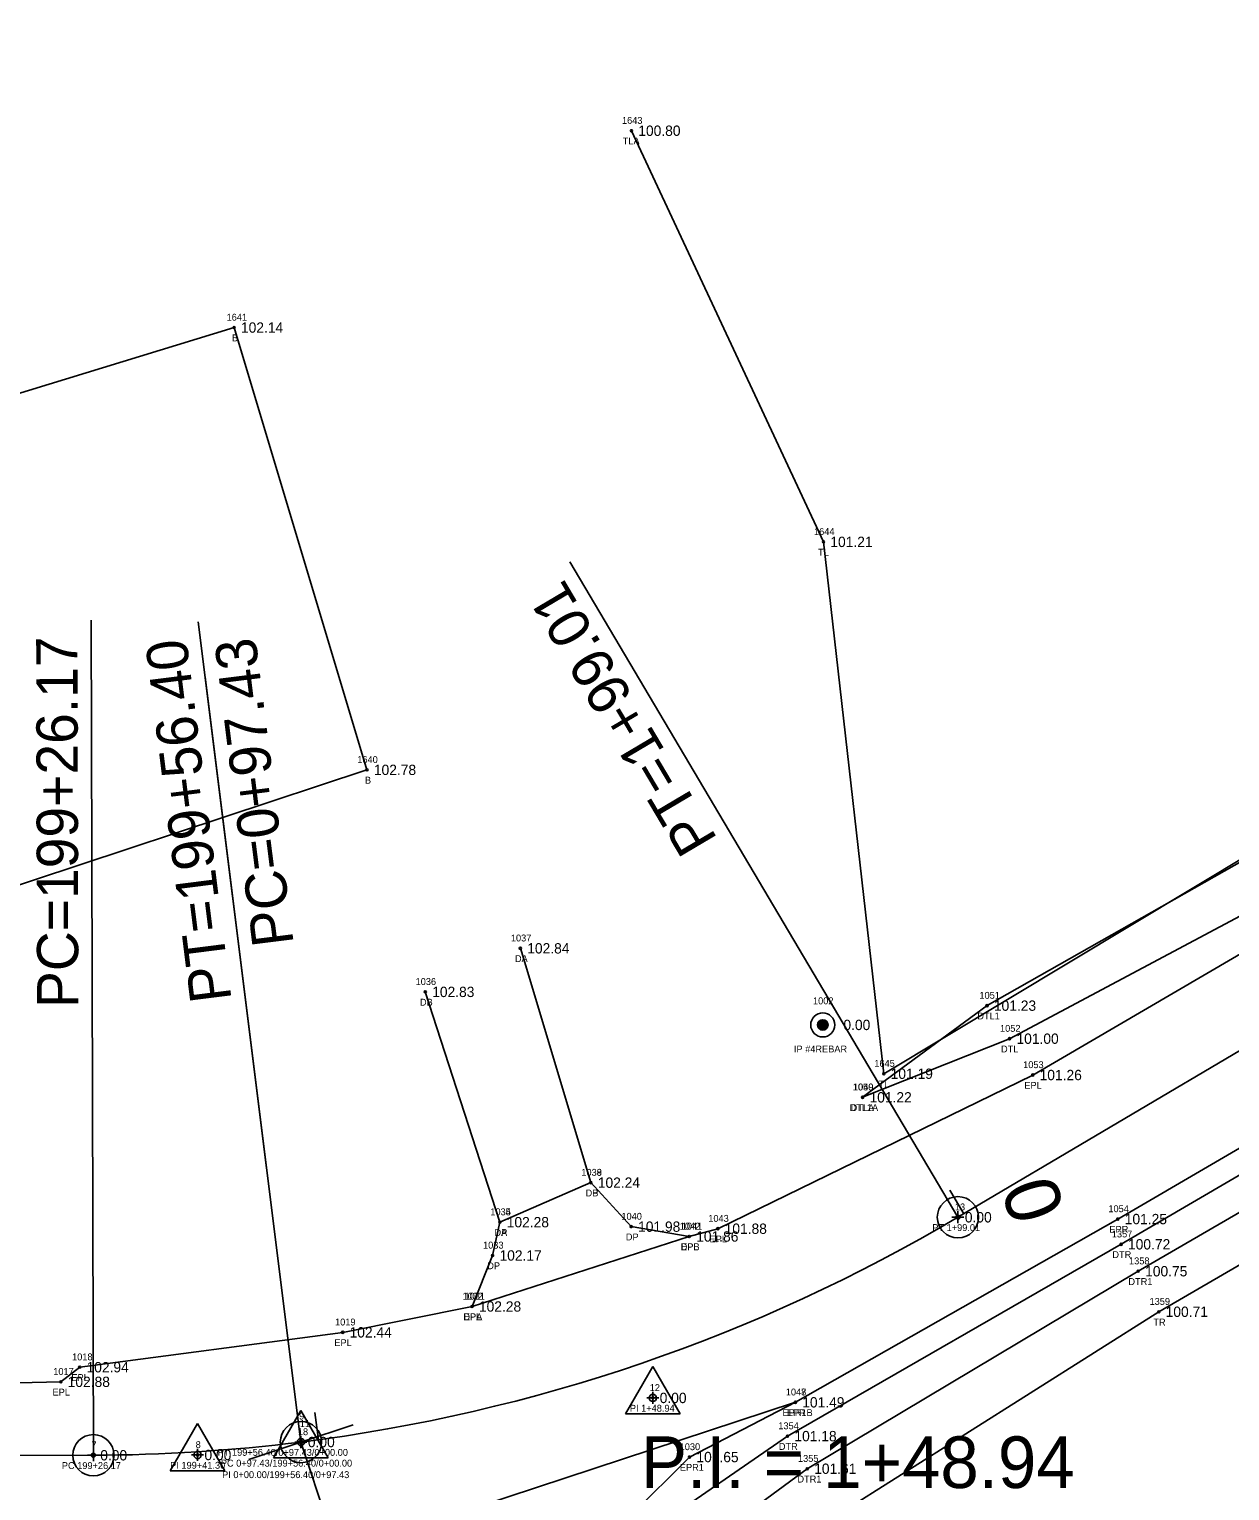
# Model space of a CAD drawing. Extents: x 2529517 to 2532038, y 935000 to 936944.
# Drawn here: x 2530422.1 to 2530596.5, y 935585.6 to 935798 of the extents above; entities that cross this region are included whole.
import ezdxf

# ---------------------------------------------------------------- set-up
doc = ezdxf.new("R2010")
doc.units = 0
for name, color, linetype in [('Default', 7, 'Continuous'), ('RD_EX_Bldg', 7, 'Continuous'), ('RD_EX_Bldg_txCode', 7, 'Continuous'), ('RD_EX_Driveway', 7, 'Continuous'), ('RD_EX_Driveway_txCode', 7, 'Continuous'), ('RD_EX_DV_Prop_txCode', 7, 'Continuous'), ('RD_EX_DV_PropPin', 7, 'Continuous'), ('RD_EX_H2O', 7, 'Continuous'), ('RD_EX_H2O_txCode', 7, 'Continuous'), ('RD_EX_Road', 7, 'Continuous'), ('RD_EX_Road_txCode', 7, 'Continuous'), ('RD_EX_TX_Bldg_ELEV', 7, 'Continuous'), ('RD_EX_TX_Driveway_ELEV', 7, 'Continuous'), ('RD_EX_TX_DV_Prop_ELEV', 7, 'Continuous'), ('RD_EX_TX_H2O_ELEV', 7, 'Continuous'), ('RD_EX_TX_Road_ELEV', 7, 'Continuous'), ('RD_EX_TX_VEG_ELEV', 7, 'Continuous'), ('RD_EX_VEG', 7, 'Continuous'), ('RD_EX_VEG_txCode', 7, 'Continuous'), ('RD_HC_Cl', 7, 'Continuous'), ('RD_HC_Data', 7, 'Continuous'), ('RD_HC_Data_Tic', 7, 'Continuous'), ('RD_HC_Survey_ELEV', 7, 'Continuous'), ('RD_HC_TX_Sta50', 7, 'Continuous'), ('RD_HC_txCode', 7, 'Continuous'), ('RD_SMD_Locator', 7, 'Continuous')]:
    doc.layers.add(name, color=color, linetype=linetype)

msp = doc.modelspace()

# ---------------------------------------------------------------- linework, layer by layer
at = {"layer": 'Default'}
for p, q in [((2530557.05, 935625.34), (2531768.07, 936342.55)), ((2530557.92, 935625.34), (2530556.17, 935625.34)), ((2530557.05, 935626.22), (2530557.05, 935624.47)), ((2530512.72, 935599.97), (2530512.72, 935598.22)), ((2530513.6, 935599.09), (2530511.85, 935599.09)), ((2530461.61, 935593.56), (2530461.61, 935591.81)), ((2530461.61, 935593.56), (2530461.61, 935591.81)), ((2530431.45, 935591.64), (2530431.45, 935589.89)), ((2530446.59, 935591.68), (2530446.59, 935589.93)), ((2530462.48, 935592.68), (2530460.73, 935592.68)), ((2530462.48, 935592.68), (2530460.73, 935592.68)), ((2530461.61, 935592.68), (2530556.12, 935307.96)), ((2530229.26, 935590.22), (2530431.45, 935590.76)), ((2530432.33, 935590.76), (2530430.58, 935590.76)), ((2530447.47, 935590.8), (2530445.72, 935590.8))]:
    msp.add_line(p, q, dxfattribs=at)
for start, end in [(277.1442, 300.6357), (277.1442, 300.6357), (270.1522, 277.1442), (270.1522, 277.1442)]:
    msp.add_arc((2530430.8, 935838.52), 247.76, start, end, dxfattribs=at)
at = {"layer": 'RD_EX_Bldg'}
msp.add_lwpolyline([(2530389.74, 935735.57), (2530408.79, 935669.73), (2530471.2, 935690.35), (2530451.89, 935754.62), (2530389.74, 935735.57)], dxfattribs=at)
at = {"layer": 'RD_EX_Driveway'}
for p, q in [((2530493.48, 935664.42), (2530503.73, 935630.37)), ((2530490.5, 935624.63), (2530479.67, 935658.09))]:
    msp.add_line(p, q, dxfattribs=at)
msp.add_lwpolyline([(2530486.46, 935612.38), (2530489.45, 935619.79), (2530490.5, 935624.63), (2530503.73, 935630.37), (2530509.58, 935623.98), (2530518.02, 935622.55)], dxfattribs=at)
at = {"layer": 'RD_EX_DV_PropPin'}
for p, q in [((2530536.68, 935653.1), (2530536.68, 935653.49)), ((2530536.71, 935653), (2530536.71, 935653.59)), ((2530536.75, 935652.92), (2530536.75, 935653.66)), ((2530536.78, 935652.87), (2530536.78, 935653.72)), ((2530536.82, 935652.82), (2530536.82, 935653.77)), ((2530536.85, 935652.78), (2530536.85, 935653.81)), ((2530536.89, 935652.74), (2530536.89, 935653.84)), ((2530536.92, 935652.71), (2530536.92, 935653.88)), ((2530536.96, 935652.68), (2530536.96, 935653.9)), ((2530536.99, 935652.66), (2530536.99, 935653.93)), ((2530537.03, 935652.64), (2530537.03, 935653.95)), ((2530537.06, 935652.62), (2530537.06, 935653.97)), ((2530537.1, 935652.6), (2530537.1, 935653.99)), ((2530537.13, 935652.59), (2530537.13, 935654)), ((2530537.17, 935652.57), (2530537.17, 935654.01)), ((2530537.2, 935652.56), (2530537.2, 935654.03)), ((2530537.24, 935652.55), (2530537.24, 935654.03)), ((2530537.27, 935652.55), (2530537.27, 935654.04)), ((2530537.31, 935652.54), (2530537.31, 935654.05)), ((2530537.34, 935652.54), (2530537.34, 935654.05)), ((2530537.38, 935652.53), (2530537.38, 935654.05)), ((2530537.41, 935652.53), (2530537.41, 935654.06)), ((2530537.45, 935652.53), (2530537.45, 935654.05)), ((2530537.48, 935652.54), (2530537.48, 935654.05)), ((2530537.52, 935652.54), (2530537.52, 935654.05)), ((2530537.55, 935652.55), (2530537.55, 935654.04)), ((2530537.59, 935652.55), (2530537.59, 935654.03)), ((2530537.62, 935652.56), (2530537.62, 935654.03)), ((2530537.66, 935652.57), (2530537.66, 935654.01)), ((2530537.69, 935652.59), (2530537.69, 935654)), ((2530537.73, 935652.6), (2530537.73, 935653.99)), ((2530537.76, 935652.62), (2530537.76, 935653.97)), ((2530537.8, 935652.64), (2530537.8, 935653.95)), ((2530537.83, 935652.66), (2530537.83, 935653.93)), ((2530537.87, 935652.68), (2530537.87, 935653.9)), ((2530537.9, 935652.71), (2530537.9, 935653.88)), ((2530537.94, 935652.74), (2530537.94, 935653.84)), ((2530537.97, 935652.78), (2530537.97, 935653.81)), ((2530538.01, 935652.82), (2530538.01, 935653.77)), ((2530538.04, 935652.87), (2530538.04, 935653.72)), ((2530538.08, 935652.92), (2530538.08, 935653.66)), ((2530538.11, 935653), (2530538.11, 935653.59)), ((2530538.15, 935653.1), (2530538.15, 935653.49))]:
    msp.add_line(p, q, dxfattribs=at)
for radius in [1.75, 0.761]:
    msp.add_circle((2530537.41, 935653.29), radius, dxfattribs=at)
at = {"layer": 'RD_EX_H2O'}
for points in [[(2530543.2, 935642.77), (2530561.27, 935656.09), (2530603.32, 935679.95), (2530687.23, 935730.15), (2530719.54, 935749.07), (2530726.45, 935748.92)], [(2530543.2, 935642.77), (2530564.55, 935651.29), (2530607.02, 935673.87), (2530692.01, 935723.47), (2530725.54, 935743.2), (2530726.45, 935748.92)], [(2530585.61, 935271.89), (2530554.63, 935366.84), (2530523, 935462.44), (2530497.71, 935534.53), (2530497.63, 935550.35), (2530501.9, 935567.07), (2530512.76, 935580.06), (2530532.29, 935593.54), (2530580.75, 935621.41), (2530622.78, 935645.99), (2530706.38, 935694.8)], [(2530592.81, 935273.73), (2530561.2, 935369.39), (2530529.39, 935464.13), (2530504.24, 935535.46), (2530502.94, 935549.83), (2530506.75, 935563.82), (2530516.63, 935575.2), (2530535.16, 935588.8), (2530583.24, 935617.5), (2530624.86, 935641.7), (2530708.31, 935690.59), (2530708.33, 935693.17), (2530706.38, 935694.8)]]:
    msp.add_lwpolyline(points, dxfattribs=at)
at = {"layer": 'RD_EX_Road'}
for points in [[(2530213.13, 935600.16), (2530313.8, 935600.81), (2530414.15, 935601.13), (2530426.72, 935601.43), (2530429.46, 935603.55), (2530467.67, 935608.62), (2530486.46, 935612.38), (2530518.02, 935622.55), (2530522.16, 935623.68), (2530567.91, 935646.01), (2530609.3, 935670.15), (2530695.46, 935720.02), (2530775.85, 935769.27), (2530868.29, 935824.03), (2530924.84, 935856.95), (2530956.21, 935875.82), (2531040.72, 935926.38), (2531079.45, 935947.76)], [(2530212.44, 935579.72), (2530312.61, 935580.14), (2530402.98, 935580.64), (2530451.06, 935579.53), (2530466.91, 935580.35), (2530487.45, 935583.29), (2530533.43, 935598.45), (2530580.28, 935625.08), (2530621.69, 935649.23), (2530704.62, 935698.35), (2530718.67, 935706.38), (2530795.45, 935752.36), (2530871.33, 935796.67), (2530882.4, 935803.04), (2530947.17, 935842.26), (2530966, 935852.42), (2530992.72, 935868), (2531009.49, 935879.01), (2531052.39, 935904.85), (2531090.88, 935928.23)], [(2530591.21, 935242.46), (2530571.43, 935300.61), (2530549.4, 935366.29), (2530518.07, 935460.9), (2530493.7, 935533.55), (2530494.46, 935557.42), (2530501.12, 935573.63), (2530518.05, 935590.5), (2530533.43, 935598.45)]]:
    msp.add_lwpolyline(points, dxfattribs=at)
at = {"layer": 'RD_EX_VEG'}
for points in [[(2530509.61, 935783.22), (2530537.51, 935723.48), (2530546.27, 935646.2), (2530689.77, 935732.43), (2530734.63, 935758.06), (2530721.39, 935783.29)], [(2530523.95, 935565.79), (2530539.5, 935582.04), (2530586.22, 935611.61), (2530720.44, 935689.62), (2530802.59, 935736.49), (2530863.89, 935770.01)]]:
    msp.add_lwpolyline(points, dxfattribs=at)
at = {"layer": 'RD_HC_Cl'}
for p, q in [((2530557.05, 935625.34), (2531768.07, 936342.55)), ((2530461.61, 935592.68), (2530556.12, 935307.96)), ((2530229.26, 935590.22), (2530431.45, 935590.76))]:
    msp.add_line(p, q, dxfattribs=at)
for start, end in [(277.1442, 300.6357), (270.1522, 277.1442)]:
    msp.add_arc((2530430.8, 935838.52), 247.76, start, end, dxfattribs=at)
at = {"layer": 'RD_HC_Data'}
for p, q in [((2530557.05, 935625.34), (2530500.65, 935720.56)), ((2530431.45, 935590.76), (2530431.13, 935712.1)), ((2530461.61, 935592.68), (2530446.67, 935711.87)), ((2530461.61, 935592.68), (2530447.68, 935703.85)), ((2530508.75, 935596.8), (2530512.72, 935603.68)), ((2530512.72, 935603.68), (2530516.69, 935596.8)), ((2530457.64, 935590.39), (2530461.61, 935597.27)), ((2530461.61, 935597.27), (2530465.58, 935590.39)), ((2530508.75, 935596.8), (2530516.69, 935596.8)), ((2530442.62, 935588.51), (2530446.59, 935595.39)), ((2530446.59, 935595.39), (2530450.56, 935588.51)), ((2530457.64, 935590.39), (2530465.58, 935590.39)), ((2530442.62, 935588.51), (2530450.56, 935588.51))]:
    msp.add_line(p, q, dxfattribs=at)
for centre, radius in [((2530557.05, 935625.34), 3), ((2530557.05, 935625.34), 0.282), ((2530512.72, 935599.09), 0.529), ((2530461.61, 935592.68), 3), ((2530461.61, 935592.68), 3), ((2530431.45, 935590.76), 3), ((2530446.59, 935590.8), 0.529), ((2530461.61, 935592.68), 0.529), ((2530461.61, 935592.68), 0.282), ((2530461.61, 935592.68), 0.282), ((2530431.45, 935590.76), 0.282)]:
    msp.add_circle(centre, radius, dxfattribs=at)
at = {"layer": 'RD_HC_Data_Tic'}
for p, q in [((2530557.9, 935625.84), (2530555.86, 935629.29)), ((2530464.16, 935593.02), (2530463.62, 935596.98)), ((2530461.61, 935592.68), (2530469.2, 935595.2)), ((2530461.61, 935592.68), (2530454.02, 935590.16))]:
    msp.add_line(p, q, dxfattribs=at)
at = {"layer": 'RD_SMD_Locator'}
for centre in [(2530509.61, 935783.22), (2530451.89, 935754.62), (2530537.51, 935723.48), (2530471.2, 935690.35), (2530493.48, 935664.42), (2530479.67, 935658.09), (2530561.27, 935656.09), (2530537.41, 935653.29), (2530564.55, 935651.29), (2530546.27, 935646.2), (2530567.91, 935646.01), (2530543.2, 935642.77), (2530543.2, 935642.77), (2530503.73, 935630.37), (2530503.73, 935630.37), (2530557.05, 935625.34), (2530580.28, 935625.08), (2530490.5, 935624.63), (2530490.5, 935624.63), (2530509.58, 935623.98), (2530522.16, 935623.68), (2530518.02, 935622.55), (2530518.02, 935622.55), (2530580.75, 935621.41), (2530489.45, 935619.79), (2530583.24, 935617.5), (2530486.46, 935612.38), (2530486.46, 935612.38), (2530586.22, 935611.61), (2530467.67, 935608.62), (2530429.46, 935603.55), (2530426.72, 935601.43), (2530512.72, 935599.09), (2530533.43, 935598.45), (2530533.43, 935598.45), (2530532.29, 935593.54), (2530461.61, 935592.68), (2530461.61, 935592.68), (2530461.61, 935592.68), (2530431.45, 935590.76), (2530446.59, 935590.8), (2530518.05, 935590.5), (2530535.16, 935588.8)]:
    msp.add_circle(centre, 0.15, dxfattribs=at)

# ---------------------------------------------------------------- texts
at = {"layer": 'RD_EX_Bldg_txCode'}
for s, p in [('1641', (2530450.8, 935755.62)), ('B', (2530451.58, 935752.62)), ('1640', (2530469.79, 935691.35)), ('B', (2530470.9, 935688.35))]:
    msp.add_text(s, height=1, dxfattribs=at).set_placement(p)
at = {"layer": 'RD_EX_Driveway_txCode'}
for s, p in [('1037', (2530492.1, 935665.42)), ('DA', (2530492.69, 935662.42)), ('1036', (2530478.26, 935659.09)), ('DB', (2530478.89, 935656.09)), ('1038', (2530502.34, 935631.37)), ('1039', (2530502.34, 935631.37)), ('DB', (2530502.95, 935628.37)), ('DP', (2530502.95, 935628.37)), ('1034', (2530489.12, 935625.63)), ('1035', (2530489.12, 935625.63)), ('1040', (2530508.16, 935624.98)), ('DA', (2530489.71, 935622.63)), ('DP', (2530489.72, 935622.63)), ('1041', (2530516.92, 935623.55)), ('1033', (2530488.06, 935620.79)), ('DP', (2530508.8, 935621.98)), ('DPB', (2530516.77, 935620.55)), ('DP', (2530488.67, 935617.79)), ('1032', (2530485.08, 935613.38)), ('DPA', (2530485.2, 935610.38))]:
    msp.add_text(s, height=1, dxfattribs=at).set_placement(p)
at = {"layer": 'RD_EX_DV_Prop_txCode'}
for s, p in [('1002', (2530535.99, 935656.29)), ('IP #4REBAR', (2530533.22, 935649.29))]:
    msp.add_text(s, height=1, dxfattribs=at).set_placement(p)
at = {"layer": 'RD_EX_H2O_txCode'}
for s, p in [('1051', (2530560.17, 935657.09)), ('DTL1', (2530559.86, 935654.09)), ('1052', (2530563.16, 935652.29)), ('DTL', (2530563.3, 935649.29)), ('1050', (2530541.77, 935643.77)), ('1049', (2530541.81, 935643.77)), ('DTL1A', (2530541.3, 935640.77)), ('DTLA', (2530541.46, 935640.77)), ('1357', (2530579.4, 935622.41)), ('DTR', (2530579.48, 935619.41)), ('1358', (2530581.9, 935618.5)), ('DTR1', (2530581.81, 935615.5)), ('1354', (2530530.95, 935594.54)), ('DTR', (2530531.03, 935591.54)), ('1355', (2530533.81, 935589.8)), ('DTR1', (2530533.73, 935586.8))]:
    msp.add_text(s, height=1, dxfattribs=at).set_placement(p)
at = {"layer": 'RD_EX_Road_txCode'}
for s, p in [('1053', (2530566.52, 935647.01)), ('EPL', (2530566.7, 935644.01)), ('1043', (2530520.78, 935624.68)), ('1054', (2530578.9, 935626.08)), ('1042', (2530516.64, 935623.55)), ('EPR', (2530579.05, 935623.08)), ('EPL', (2530516.82, 935620.55)), ('EPL', (2530520.96, 935621.68)), ('1031', (2530485.36, 935613.38)), ('1019', (2530466.56, 935609.62)), ('EPL', (2530485.26, 935610.38)), ('EPL', (2530466.46, 935606.62)), ('1018', (2530428.36, 935604.55)), ('1017', (2530425.62, 935602.43)), ('EPL', (2530428.26, 935601.55)), ('EPL', (2530425.52, 935599.43)), ('1047', (2530532.04, 935599.45)), ('1048', (2530532.04, 935599.45)), ('EPR1B', (2530531.56, 935596.45)), ('EPR', (2530532.2, 935596.45)), ('1030', (2530516.62, 935591.5)), ('EPR1', (2530516.65, 935588.5))]:
    msp.add_text(s, height=1, dxfattribs=at).set_placement(p)
at = {"layer": 'RD_EX_TX_Bldg_ELEV'}
for s, p in [('102.14', (2530452.89, 935753.87)), ('102.78', (2530472.2, 935689.6))]:
    msp.add_text(s, height=1.5, dxfattribs=at).set_placement(p)
at = {"layer": 'RD_EX_TX_Driveway_ELEV'}
for s, p in [('102.84', (2530494.48, 935663.67)), ('102.83', (2530480.67, 935657.34)), ('102.24', (2530504.73, 935629.62)), ('102.24', (2530504.73, 935629.62)), ('102.28', (2530491.5, 935623.88)), ('102.28', (2530491.5, 935623.88)), ('101.98', (2530510.58, 935623.23)), ('101.86', (2530519.02, 935621.8)), ('102.17', (2530490.45, 935619.04)), ('102.28', (2530487.46, 935611.63))]:
    msp.add_text(s, height=1.5, dxfattribs=at).set_placement(p)
at = {"layer": 'RD_EX_TX_DV_Prop_ELEV'}
msp.add_text('0.00', height=1.5, dxfattribs=at).set_placement((2530540.41, 935652.54))
at = {"layer": 'RD_EX_TX_H2O_ELEV'}
for s, p in [('101.23', (2530562.27, 935655.34)), ('101.00', (2530565.55, 935650.54)), ('101.22', (2530544.2, 935642.02)), ('101.22', (2530544.2, 935642.02)), ('100.72', (2530581.75, 935620.66)), ('100.75', (2530584.24, 935616.75)), ('101.18', (2530533.29, 935592.79)), ('101.61', (2530536.16, 935588.05))]:
    msp.add_text(s, height=1.5, dxfattribs=at).set_placement(p)
at = {"layer": 'RD_EX_TX_Road_ELEV'}
for s, p in [('101.26', (2530568.91, 935645.26)), ('101.25', (2530581.28, 935624.33)), ('101.86', (2530519.02, 935621.8)), ('101.88', (2530523.16, 935622.93)), ('102.28', (2530487.46, 935611.63)), ('102.44', (2530468.67, 935607.87)), ('102.94', (2530430.46, 935602.8)), ('102.88', (2530427.72, 935600.68)), ('101.49', (2530534.43, 935597.7)), ('101.49', (2530534.43, 935597.7)), ('101.65', (2530519.05, 935589.75))]:
    msp.add_text(s, height=1.5, dxfattribs=at).set_placement(p)
at = {"layer": 'RD_EX_TX_VEG_ELEV'}
for s, p in [('100.80', (2530510.61, 935782.47)), ('101.21', (2530538.51, 935722.73)), ('101.19', (2530547.27, 935645.45)), ('100.71', (2530587.22, 935610.86))]:
    msp.add_text(s, height=1.5, dxfattribs=at).set_placement(p)
at = {"layer": 'RD_EX_VEG_txCode'}
for s, p in [('1643', (2530508.24, 935784.22)), ('TLA', (2530508.35, 935781.22)), ('1644', (2530536.14, 935724.48)), ('TL', (2530536.73, 935721.48)), ('1645', (2530544.9, 935647.2)), ('TL', (2530545.5, 935644.2)), ('1359', (2530584.88, 935612.61)), ('TR', (2530585.43, 935609.61))]:
    msp.add_text(s, height=1, dxfattribs=at).set_placement(p)
at = {"layer": 'RD_HC_Data'}
for s, rotation, p in [('PT=1+99.01', 120.6357, (2530522.2, 935680.25)), ('PC=199+26.17', 90.1522, (2530429.28, 935655.76)), ('PT=199+56.40', 97.1442, (2530451.54, 935656.93)), ('PC=0+97.43', 97.1442, (2530460.57, 935665.07))]:
    msp.add_text(s, height=6, rotation=rotation, dxfattribs=at).set_placement(p)
msp.add_text('P.I. = 1+48.94', height=7.5, dxfattribs=at).set_placement((2530511, 935586))
at = {"layer": 'RD_HC_Survey_ELEV'}
for p in [(2530558.05, 935624.59), (2530513.72, 935598.34), (2530462.61, 935591.93), (2530462.61, 935591.93), (2530462.61, 935591.93), (2530432.45, 935590.01), (2530447.59, 935590.05)]:
    msp.add_text('0.00', height=1.5, dxfattribs=at).set_placement(p)
at = {"layer": 'RD_HC_TX_Sta50'}
msp.add_text('0', height=8, rotation=288.3628, dxfattribs=at).set_placement((2530563.21, 935629.42))
at = {"layer": 'RD_HC_txCode'}
for s, p in [('13', (2530556.6, 935626.34)), ('PT 1+99.01', (2530553.32, 935623.34)), ('12', (2530512.27, 935600.09)), ('PI 1+48.94', (2530509.39, 935597.09)), ('9', (2530461.33, 935595.95)), ('11', (2530461.44, 935594.87)), ('18', (2530461.16, 935593.68)), ('7', (2530431.17, 935591.76)), ('8', (2530446.31, 935591.8)), ('PT 199+56.40/0+97.43/0+00.00', (2530449.51, 935590.68)), ('PC 199+26.17', (2530426.87, 935588.76)), ('PI 199+41.30', (2530442.61, 935588.8)), ('PC 0+97.43/199+56.40/0+00.00', (2530449.97, 935589.11)), ('PI 0+00.00/199+56.40/0+97.43', (2530450.15, 935587.44))]:
    msp.add_text(s, height=1, dxfattribs=at).set_placement(p)

doc.saveas('drawing.dxf')
